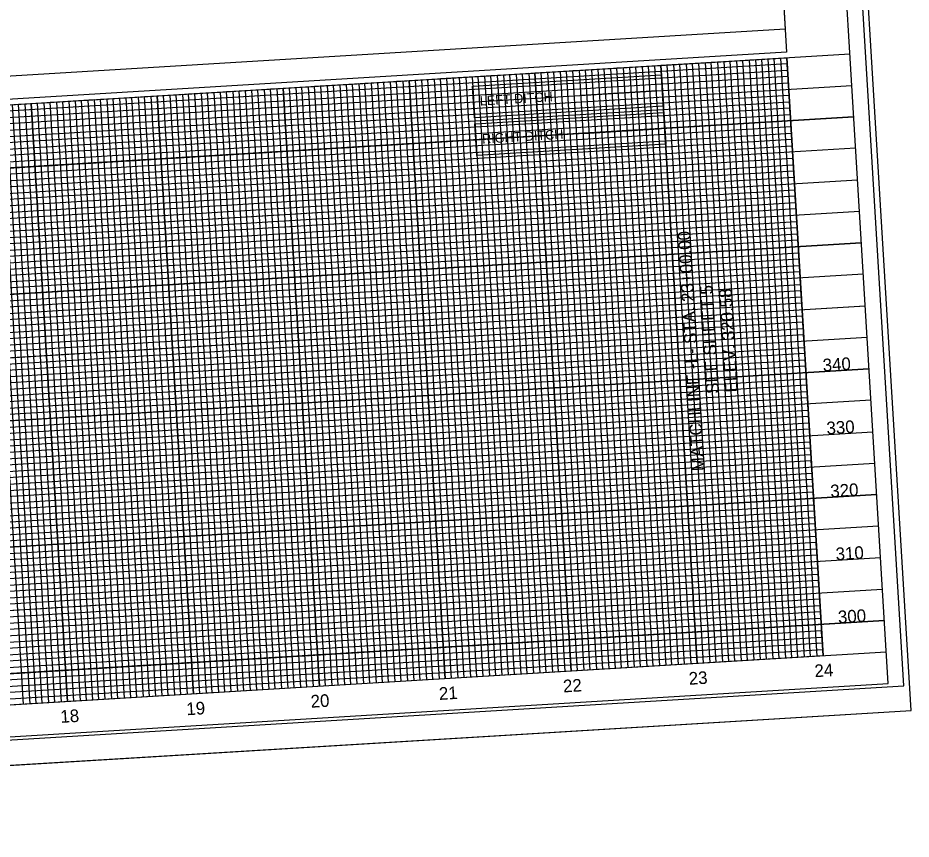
# Model space of a CAD drawing. Extents: x 2110128 to 2112690, y 669500 to 671339.
# Drawn here: x 2111812 to 2112520, y 669639 to 670290 of the extents above; entities that cross this region are included whole.
import ezdxf

# ---------------------------------------------------------------- set-up
doc = ezdxf.new("R2010")
doc.units = 0
for name, color, linetype in [('COGO Default Chain', 7, 'Continuous'), ('Exist Building', 7, 'Continuous'), ('Exist Building Leader', 7, 'Continuous'), ('Exist Other Culture Area Outline', 7, 'Continuous'), ('Exist Other Culture Fence Line Text', 7, 'Continuous'), ('Exist Other Culture Sign Leader', 7, 'Continuous'), ('Exist Roads Curbs', 7, 'Continuous'), ('Exist Roads Curbs Text', 7, 'Continuous'), ('Exist Roads EOP Other Text', 7, 'Continuous'), ('Exist Roads EOP Text', 7, 'Continuous'), ('Exist Structure Minor Footbridge', 7, 'Continuous'), ('Exist Structure Minor Pipes CMP 60 Inch', 7, 'Continuous'), ('Exist Utilities TV Hand Hole CELL', 7, 'Continuous'), ('Exist Utilities TV Test Hole SUE LOS A Text', 7, 'Continuous'), ('Exist Utilities Water Fire Hydrant CELL', 7, 'Continuous'), ('Exist Utilities Water Test Hole SUE LOS A Text', 7, 'Continuous')]:
    doc.layers.add(name, color=color, linetype=linetype)

msp = doc.modelspace()

# ---------------------------------------------------------------- linework, layer by layer
at = {"layer": 'COGO Default Chain'}
for points in [[(2112172.29, 670235.84), (2112322.01, 670244.92), (2112323.52, 670219.96), (2112173.8, 670210.89)], [(2112174.1, 670205.9), (2112323.83, 670214.97), (2112325.34, 670190.02), (2112175.61, 670180.94)]]:
    msp.add_lwpolyline(points, close=True, dxfattribs=at)
at = {"layer": 'Exist Building'}
for points in [[(2110974.03, 670170.73), (2112471.28, 670261.48)], [(2112350.29, 669778.27), (2112321.56, 670252.4), (2112371.47, 670255.43), (2112400.2, 669781.3)], [(2112450.11, 669784.32), (2112421.37, 670258.45)], [(2112250.48, 669772.22), (2112221.74, 670246.35), (2112271.65, 670249.38), (2112300.38, 669775.25)], [(2112150.66, 669766.17), (2112121.92, 670240.3), (2112171.83, 670243.33), (2112200.57, 669769.2)], [(2112050.84, 669760.12), (2112022.11, 670234.25), (2112072.02, 670237.28), (2112100.75, 669763.15)], [(2111851.21, 669748.02), (2111822.47, 670222.15), (2111872.38, 670225.18), (2111901.12, 669751.05)], [(2111951.03, 669754.07), (2111922.29, 670228.2), (2111972.2, 670231.23), (2112000.93, 669757.1)], [(2112474.31, 670211.57), (2110977.05, 670120.82), (2110980.08, 670070.92), (2112477.33, 670161.66)], [(2112480.36, 670111.75), (2110983.1, 670021.01), (2110986.13, 669971.1), (2112483.38, 670061.84)], [(2112486.41, 670011.93), (2110989.15, 669921.19), (2110992.18, 669871.28), (2112489.43, 669962.03)], [(2112492.46, 669912.12), (2110995.2, 669821.37), (2110998.23, 669771.47), (2112495.48, 669862.21)], [(2112498.51, 669812.3), (2111001.25, 669721.56)]]:
    msp.add_lwpolyline(points, dxfattribs=at)
at = {"layer": 'Exist Building Leader'}
for points in [[(2111024.54, 670163.78), (2112421.98, 670248.47), (2112421.68, 670253.46), (2111024.24, 670168.77)], [(2112355.28, 669778.57), (2112326.55, 670252.7), (2112331.54, 670253.01), (2112360.27, 669778.88)], [(2112365.27, 669779.18), (2112336.53, 670253.31), (2112341.52, 670253.61), (2112370.26, 669779.48)], [(2112380.24, 669780.09), (2112351.5, 670254.22), (2112356.49, 670254.52), (2112385.23, 669780.39)], [(2112390.22, 669780.69), (2112361.48, 670254.82), (2112366.48, 670255.12), (2112395.21, 669780.99)], [(2112405.19, 669781.6), (2112376.46, 670255.73), (2112381.45, 670256.03), (2112410.18, 669781.9)], [(2112415.17, 669782.2), (2112386.44, 670256.33), (2112391.43, 670256.64), (2112420.16, 669782.51)], [(2112430.15, 669783.11), (2112401.41, 670257.24), (2112406.4, 670257.54), (2112435.14, 669783.41)], [(2112440.13, 669783.72), (2112411.39, 670257.85), (2112416.38, 670258.15), (2112445.12, 669784.02)], [(2112240.49, 669771.62), (2112211.76, 670245.75), (2112216.75, 670246.05), (2112245.49, 669771.92)], [(2112255.47, 669772.52), (2112226.73, 670246.65), (2112231.72, 670246.96), (2112260.46, 669772.83)], [(2112265.45, 669773.13), (2112236.71, 670247.26), (2112241.7, 670247.56), (2112270.44, 669773.43)], [(2112280.42, 669774.04), (2112251.69, 670248.17), (2112256.68, 670248.47), (2112285.41, 669774.34)], [(2112290.4, 669774.64), (2112261.67, 670248.77), (2112266.66, 670249.07), (2112295.39, 669774.94)], [(2112305.38, 669775.55), (2112276.64, 670249.68), (2112281.63, 670249.98), (2112310.37, 669775.85)], [(2112315.36, 669776.15), (2112286.62, 670250.28), (2112291.61, 670250.59), (2112320.35, 669776.46)], [(2112330.33, 669777.06), (2112301.59, 670251.19), (2112306.59, 670251.49), (2112335.32, 669777.36)], [(2112340.31, 669777.67), (2112311.58, 670251.8), (2112316.57, 670252.1), (2112345.3, 669777.97)], [(2111025.15, 670153.79), (2112422.58, 670238.49), (2112422.28, 670243.48), (2111024.85, 670158.79)], [(2112130.7, 669764.96), (2112101.96, 670239.09), (2112106.95, 670239.4), (2112135.69, 669765.27)], [(2112140.68, 669765.57), (2112111.94, 670239.7), (2112116.93, 670240), (2112145.67, 669765.87)], [(2112155.65, 669766.47), (2112126.91, 670240.6), (2112131.91, 670240.91), (2112160.64, 669766.78)], [(2112165.63, 669767.08), (2112136.9, 670241.21), (2112141.89, 670241.51), (2112170.62, 669767.38)], [(2112180.6, 669767.99), (2112151.87, 670242.12), (2112156.86, 670242.42), (2112185.59, 669768.29)], [(2112190.59, 669768.59), (2112161.85, 670242.72), (2112166.84, 670243.02), (2112195.58, 669768.89)], [(2112205.56, 669769.5), (2112176.82, 670243.63), (2112181.81, 670243.93), (2112210.55, 669769.8)], [(2112215.54, 669770.1), (2112186.8, 670244.23), (2112191.8, 670244.54), (2112220.53, 669770.41)], [(2112230.51, 669771.01), (2112201.78, 670245.14), (2112206.77, 670245.44), (2112235.5, 669771.31)], [(2112005.92, 669757.4), (2111977.19, 670231.53), (2111982.18, 670231.83), (2112010.92, 669757.7)], [(2112015.91, 669758.01), (2111987.17, 670232.14), (2111992.16, 670232.44), (2112020.9, 669758.31)], [(2112030.88, 669758.91), (2112002.14, 670233.04), (2112007.13, 670233.35), (2112035.87, 669759.22)], [(2112040.86, 669759.52), (2112012.13, 670233.65), (2112017.12, 670233.95), (2112045.85, 669759.82)], [(2112055.83, 669760.43), (2112027.1, 670234.56), (2112032.09, 670234.86), (2112060.82, 669760.73)], [(2112065.81, 669761.03), (2112037.08, 670235.16), (2112042.07, 670235.46), (2112070.81, 669761.33)], [(2112080.79, 669761.94), (2112052.05, 670236.07), (2112057.04, 670236.37), (2112085.78, 669762.24)], [(2112090.77, 669762.54), (2112062.03, 670236.67), (2112067.02, 670236.98), (2112095.76, 669762.85)], [(2112105.74, 669763.45), (2112077.01, 670237.58), (2112082, 670237.88), (2112110.73, 669763.75)], [(2112115.72, 669764.06), (2112086.99, 670238.19), (2112091.98, 670238.49), (2112120.71, 669764.36)], [(2111026.06, 670138.82), (2112423.49, 670223.52), (2112423.19, 670228.51), (2111025.75, 670143.81)], [(2111891.14, 669750.44), (2111862.4, 670224.57), (2111867.39, 670224.88), (2111896.13, 669750.75)], [(2111906.11, 669751.35), (2111877.37, 670225.48), (2111882.36, 670225.78), (2111911.1, 669751.65)], [(2111916.09, 669751.96), (2111887.35, 670226.09), (2111892.35, 670226.39), (2111921.08, 669752.26)], [(2111931.06, 669752.86), (2111902.33, 670226.99), (2111907.32, 670227.3), (2111936.05, 669753.17)], [(2111941.04, 669753.47), (2111912.31, 670227.6), (2111917.3, 670227.9), (2111946.03, 669753.77)], [(2111956.02, 669754.38), (2111927.28, 670228.51), (2111932.27, 670228.81), (2111961.01, 669754.68)], [(2111966, 669754.98), (2111937.26, 670229.11), (2111942.25, 670229.41), (2111970.99, 669755.28)], [(2111980.97, 669755.89), (2111952.24, 670230.02), (2111957.23, 670230.32), (2111985.96, 669756.19)], [(2111990.95, 669756.49), (2111962.22, 670230.62), (2111967.21, 670230.93), (2111995.94, 669756.8)], [(2111026.66, 670128.84), (2112424.1, 670213.53), (2112423.79, 670218.52), (2111026.36, 670133.83)], [(2111816.27, 669745.91), (2111787.54, 670220.04), (2111792.53, 670220.34), (2111821.26, 669746.21)], [(2111831.25, 669746.81), (2111802.51, 670220.94), (2111807.5, 670221.25), (2111836.24, 669747.12)], [(2111841.23, 669747.42), (2111812.49, 670221.55), (2111817.48, 670221.85), (2111846.22, 669747.72)], [(2111856.2, 669748.33), (2111827.46, 670222.46), (2111832.45, 670222.76), (2111861.19, 669748.63)], [(2111866.18, 669748.93), (2111837.45, 670223.06), (2111842.44, 670223.36), (2111871.17, 669749.23)], [(2111881.15, 669749.84), (2111852.42, 670223.97), (2111857.41, 670224.27), (2111886.14, 669750.14)], [(2111027.57, 670113.87), (2112425, 670198.56), (2112424.7, 670203.55), (2111027.27, 670118.86)], [(2111028.17, 670103.89), (2112425.61, 670188.58), (2112425.31, 670193.57), (2111027.87, 670108.88)], [(2111029.08, 670088.91), (2112426.52, 670173.61), (2112426.21, 670178.6), (2111028.78, 670093.9)], [(2111029.69, 670078.93), (2112427.12, 670163.63), (2112426.82, 670168.62), (2111029.38, 670083.92)], [(2111030.29, 670068.95), (2112427.73, 670153.64)], [(2111030.9, 670058.97), (2112428.33, 670143.66), (2112428.03, 670148.65), (2111030.59, 670063.96)], [(2111031.8, 670044), (2112429.24, 670128.69), (2112428.63, 670138.67), (2111031.2, 670053.98)], [(2111032.41, 670034.01), (2112429.84, 670118.71), (2112429.54, 670123.7), (2111032.11, 670039)], [(2111033.32, 670019.04), (2112430.75, 670103.73), (2112430.15, 670113.72), (2111032.71, 670029.02)], [(2111033.92, 670009.06), (2112431.36, 670093.75), (2112431.05, 670098.74), (2111033.62, 670014.05)], [(2111034.83, 669994.09), (2112432.26, 670078.78), (2112431.66, 670088.76), (2111034.22, 670004.07)], [(2111035.43, 669984.11), (2112432.87, 670068.8), (2112432.57, 670073.79), (2111035.13, 669989.1)], [(2111036.34, 669969.13), (2112433.78, 670053.83), (2112433.17, 670063.81), (2111035.74, 669979.11)], [(2111036.94, 669959.15), (2112434.38, 670043.84), (2112434.08, 670048.84), (2111036.64, 669964.14)], [(2111037.85, 669944.18), (2112435.29, 670028.87), (2112434.68, 670038.85), (2111037.25, 669954.16)], [(2111038.46, 669934.2), (2112435.89, 670018.89), (2112435.59, 670023.88), (2111038.15, 669939.19)], [(2111039.36, 669919.22), (2112436.8, 670003.92), (2112436.2, 670013.9), (2111038.76, 669929.21)], [(2111039.97, 669909.24), (2112437.41, 669993.94), (2112437.1, 669998.93), (2111039.67, 669914.23)], [(2111040.88, 669894.27), (2112438.31, 669978.96), (2112437.71, 669988.95), (2111040.27, 669904.25)], [(2111041.48, 669884.29), (2112438.92, 669968.98), (2112438.62, 669973.97), (2111041.18, 669889.28)], [(2111042.39, 669869.32), (2112439.83, 669954.01), (2112439.22, 669963.99), (2111041.78, 669879.3)], [(2111042.99, 669859.33), (2112440.43, 669944.03), (2112440.13, 669949.02), (2111042.69, 669864.33)], [(2111043.9, 669844.36), (2112441.34, 669929.06), (2112440.73, 669939.04), (2111043.3, 669854.34)], [(2111044.51, 669834.38), (2112441.94, 669919.07), (2112441.64, 669924.06), (2111044.2, 669839.37)], [(2111045.41, 669819.41), (2112442.85, 669904.1), (2112442.25, 669914.08), (2111044.81, 669829.39)], [(2111046.02, 669809.43), (2112443.46, 669894.12), (2112443.15, 669899.11), (2111045.72, 669814.42)], [(2111046.93, 669794.45), (2112444.36, 669879.15), (2112443.76, 669889.13), (2111046.32, 669804.44)], [(2111047.53, 669784.47), (2112444.97, 669869.17), (2112444.67, 669874.16), (2111047.23, 669789.46)], [(2111048.44, 669769.5), (2112445.87, 669854.19), (2112445.27, 669864.17), (2111047.83, 669779.48)], [(2111052.37, 669704.62), (2112449.81, 669789.31), (2112449.5, 669794.3), (2111052.07, 669709.61), (2111051.77, 669714.6), (2112449.2, 669799.29), (2112448.9, 669804.28), (2111051.46, 669719.59), (2111051.16, 669724.58), (2111050.86, 669729.57), (2112448.29, 669814.27), (2112447.99, 669819.26), (2111050.56, 669734.56), (2111050.25, 669739.55), (2112447.69, 669824.25), (2112447.39, 669829.24), (2111049.95, 669744.55), (2111049.65, 669749.54), (2111049.35, 669754.53), (2112446.78, 669839.22), (2112446.48, 669844.21), (2111049.04, 669759.52), (2111048.74, 669764.51), (2112446.18, 669849.2)]]:
    msp.add_lwpolyline(points, dxfattribs=at)
at = {"layer": 'Exist Other Culture Area Outline'}
for p, q in [((2110975.54, 670145.78), (2112472.8, 670236.52)), ((2112475.82, 670186.61), (2110978.57, 670095.87)), ((2110981.59, 670045.96), (2112478.84, 670136.7)), ((2112481.87, 670086.8), (2110984.62, 669996.05)), ((2110987.64, 669946.15), (2112484.89, 670036.89)), ((2112487.92, 669986.98), (2110990.67, 669896.24)), ((2110993.69, 669846.33), (2112490.94, 669937.07)), ((2112493.97, 669887.16), (2110996.72, 669796.42)), ((2110999.74, 669746.51), (2112496.99, 669837.25))]:
    msp.add_line(p, q, dxfattribs=at)
for points in [[(2112375.25, 669779.78), (2112346.51, 670253.91), (2112396.42, 670256.94), (2112425.16, 669782.81)], [(2112275.43, 669773.73), (2112246.69, 670247.86), (2112296.6, 670250.89), (2112325.34, 669776.76)], [(2112075.8, 669761.64), (2112047.06, 670235.77), (2112096.97, 670238.79), (2112125.7, 669764.66)], [(2112175.61, 669767.68), (2112146.88, 670241.81), (2112196.79, 670244.84), (2112225.52, 669770.71)], [(2111975.98, 669755.59), (2111947.24, 670229.72), (2111997.15, 670232.74), (2112025.89, 669758.61)], [(2111876.16, 669749.54), (2111847.43, 670223.67), (2111897.34, 670226.69), (2111926.07, 669752.56)], [(2111776.35, 669743.49), (2111747.61, 670217.62), (2111797.52, 670220.64), (2111826.25, 669746.51)]]:
    msp.add_lwpolyline(points, dxfattribs=at)
at = {"layer": 'Exist Other Culture Fence Line Text'}
for p, q in [((2112258.42, 670228.74), (2112318.31, 670232.37)), ((2112260.26, 670198.44), (2112320.15, 670202.07)), ((2112175.01, 670190.92), (2112175.01, 670190.92))]:
    msp.add_line(p, q, dxfattribs=at)
at = {"layer": 'Exist Other Culture Sign Leader'}
msp.add_lwpolyline([(2111023.94, 670173.76), (2112421.37, 670258.45), (2112450.11, 669784.32), (2111052.67, 669699.63)], close=True, dxfattribs=at)
at = {"layer": 'Exist Roads Curbs'}
msp.add_line((2110839.44, 669639.12), (2112519.86, 669740.96), dxfattribs=at)
at = {"layer": 'Exist Roads Curbs Text'}
msp.add_line((2112500.02, 669787.35), (2111002.77, 669696.6), dxfattribs=at)
msp.add_lwpolyline([(2112438.01, 670810.47), (2110940.76, 670719.73), (2111004.28, 669671.65), (2112501.53, 669762.39)], close=True, dxfattribs=at)
at = {"layer": 'Exist Roads EOP Other Text'}
msp.add_lwpolyline([(2110851.21, 669659.87), (2112514.16, 669760.65), (2112450.34, 670813.72), (2110787.39, 670712.94)], close=True, dxfattribs=at)
at = {"layer": 'Exist Roads EOP Text'}
msp.add_line((2112327.61, 670152.58), (2112350.29, 669778.27), dxfattribs=at)
at = {"layer": 'Exist Utilities TV Hand Hole CELL'}
for p, q in [((2110974.03, 670170.73), (2112471.28, 670261.48)), ((2112371.47, 670255.43), (2112400.2, 669781.3)), ((2112421.37, 670258.45), (2112450.11, 669784.32)), ((2112221.74, 670246.35), (2112250.48, 669772.22)), ((2112271.65, 670249.38), (2112300.38, 669775.25)), ((2112321.56, 670252.4), (2112350.29, 669778.27)), ((2112121.92, 670240.3), (2112150.66, 669766.17)), ((2112171.83, 670243.33), (2112200.57, 669769.2)), ((2112022.11, 670234.25), (2112050.84, 669760.12)), ((2112072.02, 670237.28), (2112100.75, 669763.15)), ((2111872.38, 670225.18), (2111901.12, 669751.05)), ((2111922.29, 670228.2), (2111951.03, 669754.07)), ((2111972.2, 670231.23), (2112000.93, 669757.1)), ((2111822.47, 670222.15), (2111851.21, 669748.02)), ((2110977.05, 670120.82), (2112474.31, 670211.57)), ((2110980.08, 670070.92), (2112477.33, 670161.66)), ((2110983.1, 670021.01), (2112480.36, 670111.75)), ((2110986.13, 669971.1), (2112483.38, 670061.84)), ((2110989.15, 669921.19), (2112486.41, 670011.93)), ((2110992.18, 669871.28), (2112489.43, 669962.03)), ((2110995.2, 669821.37), (2112492.46, 669912.12)), ((2110998.23, 669771.47), (2112495.48, 669862.21)), ((2111001.25, 669721.56), (2112498.51, 669812.3))]:
    msp.add_line(p, q, dxfattribs=at)
at = {"layer": 'Exist Utilities TV Test Hole SUE LOS A Text'}
msp.add_lwpolyline([(2111022.58, 670196.24), (2110993.69, 670672.84), (2112191.44, 670745.43), (2112200.05, 670603.34), (2112399.74, 670615.44), (2112420.01, 670280.93)], close=True, dxfattribs=at)
at = {"layer": 'Exist Utilities Water Fire Hydrant CELL'}
msp.add_lwpolyline([(2110944.98, 670715.17), (2112189.1, 670790.57), (2112200.05, 670603.34), (2112399.74, 670615.44), (2112418.35, 670308.36), (2112421.12, 670262.68), (2110980.52, 670175.37)], close=True, dxfattribs=at)
at = {"layer": 'Exist Utilities Water Test Hole SUE LOS A Text'}
msp.add_lwpolyline([(2110839.44, 669639.12), (2112519.86, 669740.96), (2112453.62, 670833.96), (2110773.2, 670732.11)], close=True, dxfattribs=at)

# ---------------------------------------------------------------- texts
at = {"layer": 'Exist Other Culture Fence Line Text'}
for s, p in [('LEFT DITCH', (2112178.23, 670220.47)), ('RIGHT DITCH', (2112180.05, 670190.33))]:
    msp.add_text(s, height=7.485, rotation=3.46824, dxfattribs=at).set_placement(p)
at = {"layer": 'Exist Roads EOP Text'}
for s, p in [('MATCHLINE -L- STA. 23+00.00', (2112356.25, 669931.04)), ('SEE SHEET 5', (2112367.56, 669992.35)), ('ELEV. 320.58', (2112382.52, 669993.39))]:
    msp.add_text(s, height=10, rotation=93.46824, dxfattribs=at).set_placement(p)
at = {"layer": 'Exist Structure Minor Footbridge'}
for s, p in [('23', (2112343.91, 669761.4)), ('24', (2112443.57, 669767.44)), ('22', (2112244.26, 669755.36)), ('21', (2112145.89, 669749.4)), ('20', (2112044.24, 669743.24)), ('19', (2111945.74, 669737.27)), ('18', (2111845.88, 669731.22))]:
    msp.add_text(s, height=10, rotation=3.46824, dxfattribs=at).set_placement(p)
at = {"layer": 'Exist Structure Minor Pipes CMP 60 Inch'}
for s, p in [('340', (2112450.06, 670009.73)), ('330', (2112453.08, 669959.82)), ('320', (2112456.11, 669909.91)), ('310', (2112460.33, 669860.08)), ('300', (2112462.16, 669810.1))]:
    msp.add_text(s, height=10, rotation=3.46824, dxfattribs=at).set_placement(p)

doc.saveas('drawing.dxf')
